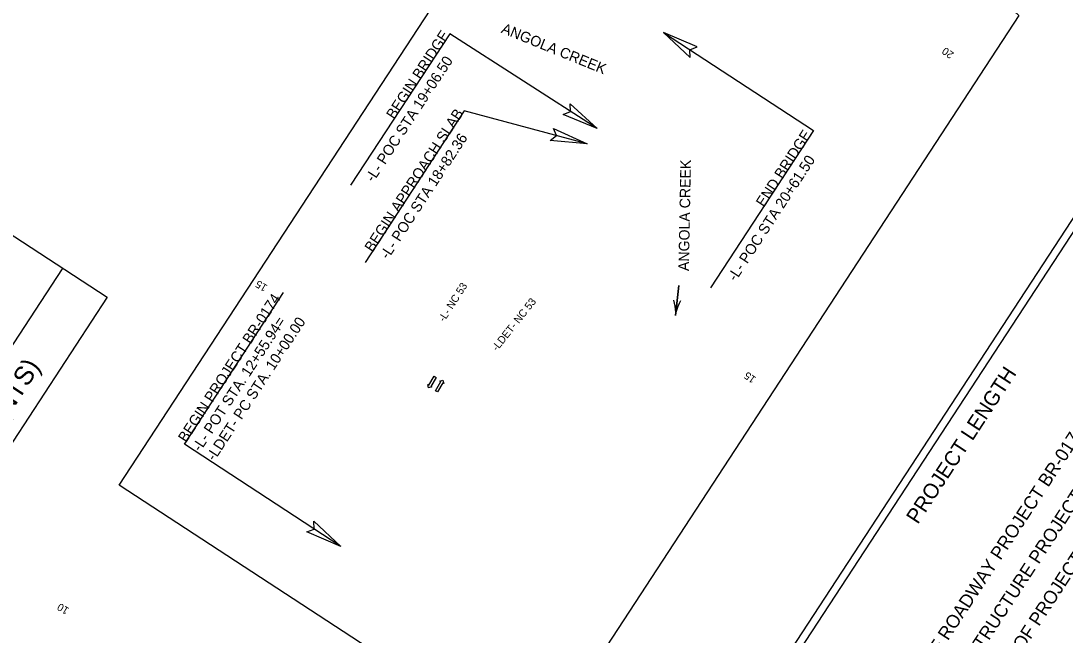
# Model space of a CAD drawing. Extents: x 1190029 to 2382315, y 163128 to 334830.
# Drawn here: x 2379548 to 2380933, y 331527 to 332342 of the extents above; entities that cross this region are included whole.
import ezdxf

# ---------------------------------------------------------------- set-up
doc = ezdxf.new("R2010")
doc.units = 0
for name, color, linetype in [('Exist Property Line', 7, 'Continuous'), ('Exist Utilities Telephone UG FO SUE LOS B', 7, 'Continuous'), ('Exist Utilities Telephone UG FO SUE LOS B Text', 7, 'Continuous'), ('P_NCDOT_Vertical_Profile_Grade_Label', 7, 'Continuous'), ('Sheet Block Title CELL', 7, 'Continuous'), ('Sheet_Plan_CELL', 7, 'Continuous')]:
    doc.layers.add(name, color=color, linetype=linetype)

msp = doc.modelspace()

# ---------------------------------------------------------------- linework, layer by layer
at = {"layer": 'Exist Utilities Telephone UG FO SUE LOS B'}
for p, q in [((2380088.8, 331858.5), (2380095.9, 331870.6)), ((2380098.8, 331868.9), (2380091.6, 331856.9)), ((2380095.9, 331870.6), (2380098.8, 331868.9)), ((2380088.7, 331855), (2380087.5, 331859.3)), ((2380087.5, 331859.3), (2380088.8, 331858.5)), ((2380092.9, 331856.1), (2380088.7, 331855)), ((2380091.6, 331856.9), (2380092.9, 331856.1)), ((2380097.7, 331851.1), (2380104.8, 331863.2)), ((2380107.7, 331861.5), (2380100.5, 331849.5)), ((2380103.6, 331863.9), (2380107.8, 331865.1)), ((2380104.8, 331863.2), (2380103.6, 331863.9)), ((2380109, 331860.7), (2380107.7, 331861.5)), ((2380107.8, 331865.1), (2380109, 331860.7)), ((2380100.5, 331849.5), (2380097.7, 331851.1))]:
    msp.add_line(p, q, dxfattribs=at)
at = {"layer": 'Exist Utilities Telephone UG FO SUE LOS B Text'}
for p, q in [((2380185.5, 330920.1), (2381876.3, 333506.5)), ((2379159.9, 332303.6), (2379662.2, 331975.2)), ((2380566, 331483.8), (2380981.8, 332119.9)), ((2379602.6, 332013.1), (2379314.3, 331572.2)), ((2379662.2, 331975.2), (2379374, 331534.3))]:
    msp.add_line(p, q, dxfattribs=at)
at = {"layer": 'Sheet Block Title CELL'}
for points in [[(2380444.8, 332307.4), (2380400.1, 332326.7), (2380435.8, 332293.2), (2380435.3, 332303.6)], [(2380276.4, 332231.9), (2380312.3, 332199), (2380267.1, 332217.9), (2380276.9, 332221.8)], [(2380254.6, 332199.3), (2380298.9, 332178.9), (2380250, 332183.1), (2380258.2, 332189.8)], [(2379936.4, 331677.8), (2379972.1, 331644.6), (2379927, 331663.9), (2379936.8, 331667.6)]]:
    msp.add_lwpolyline(points, close=True, dxfattribs=at)
at = {"layer": 'Sheet_Plan_CELL'}
for p, q in [((2380116.7, 332325), (2379985, 332123.8)), ((2380312.3, 332199), (2380116.7, 332325)), ((2380400.1, 332326.7), (2380599.3, 332196.4)), ((2380136.1, 332222.4), (2380004.4, 332021.1)), ((2380298.9, 332178.9), (2380136.1, 332222.4)), ((2380599.3, 332196.4), (2380462.6, 331987.5)), ((2379764.8, 331780.1), (2379896.3, 331981.5)), ((2380418.4, 331970.8), (2380418.4, 331970.8)), ((2379972.1, 331644.6), (2379764.8, 331780.1))]:
    msp.add_line(p, q, dxfattribs=at)
msp.add_lwpolyline([(2379678.4, 331725.7), (2380382.5, 332802.6), (2380871.9, 332349.2), (2380229.4, 331365.5)], close=True, dxfattribs=at)
msp.add_lwpolyline([(2380422.9, 331970.3), (2380421, 331966.7), (2380419.2, 331962.9), (2380417.8, 331959), (2380416.8, 331955), (2380416.2, 331950.9), (2380420.7, 331990.7), (2380416.2, 331950.9), (2380416.5, 331955), (2380416.3, 331959.2), (2380415.8, 331963.3), (2380415, 331967.4), (2380413.9, 331971.3)], dxfattribs=at)

# ---------------------------------------------------------------- texts
at = {"layer": 'Exist Property Line'}
for s, rotation, p in [('20', 144.9522, (2380786.4, 332299.1)), ('15', 149.0736, (2379875.7, 331990.6)), ('15', 144.5997, (2380523.9, 331868.3)), ('10', 149.6068, (2379612.6, 331562.1))]:
    msp.add_text(s, height=10, rotation=rotation, dxfattribs=at).set_placement(p)
at = {"layer": 'Exist Utilities Telephone UG FO SUE LOS B Text'}
for s, height, p in [('VICINITY MAP (NTS)', 25, (2379398.8, 331614.2)), ('PROJECT LENGTH', 19.999, (2380737.7, 331672.9))]:
    msp.add_text(s, height=height, rotation=56.8248, dxfattribs=at).set_placement(p)
at = {"layer": 'P_NCDOT_Vertical_Profile_Grade_Label'}
for s, rotation, p in [('-L- NC 53', 57.3093, (2380109.3, 331941.7)), ('-LDET- NC 53', 51.5455, (2380179.4, 331902.9))]:
    msp.add_text(s, height=10, rotation=rotation, dxfattribs=at).set_placement(p)
at = {"layer": 'Sheet_Plan_CELL'}
for s, height, rotation, p in [('ANGOLA CREEK', 14, 337.8471, (2380184, 332326.6)), ('BEGIN BRIDGE', 14, 56.8248, (2380043.2, 332210.3)), ('-L- POC STA 19+06.50', 14, 56.8248, (2380015.4, 332126.9)), ('BEGIN APPROACH SLAB', 14, 56.8248, (2380014.4, 332034)), ('-L- POC STA 18+82.36', 14, 56.8248, (2380034.9, 332024.5)), ('END BRIDGE', 14, 56.8248, (2380533.6, 332093.8)), ('ANGOLA CREEK', 14, 88.932, (2380434, 332009.9)), ('-L- POC STA 20+61.50', 14, 56.8248, (2380496, 331995.3)), ('BEGIN PROJECT BR-0174', 14, 56.8248, (2379767.1, 331781.5)), ('-L- POT STA. 12+55.94=', 14, 56.8248, (2379785.8, 331769.3)), ('-LDET- PC STA. 10+00.00', 14, 56.8248, (2379804.6, 331757)), ('LENGTH OF ROADWAY PROJECT BR-0174 = 0.335 MILES', 17.5, 56.8248, (2380700.8, 331401.1)), ('LENGTH OF STRUCTURE PROJECT BR-0174 = 0.029 MILES', 17.5, 56.8248, (2380738.7, 331376.3)), ('TOTAL LENGTH OF PROJECT BR-0174 = 0.364 MILES', 17.5, 56.8248, (2380776.7, 331351.5))]:
    msp.add_text(s, height=height, rotation=rotation, dxfattribs=at).set_placement(p)

doc.saveas('drawing.dxf')
